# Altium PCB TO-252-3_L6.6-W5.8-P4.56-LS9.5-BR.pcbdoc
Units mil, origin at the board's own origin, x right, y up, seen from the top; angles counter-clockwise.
Board outline 938.23 x 780 mil, 2 copper layers (Top Layer, Bottom Layer), stack 0 mil thick; 1 components, 0 nets, 3 pads, 0 vias.
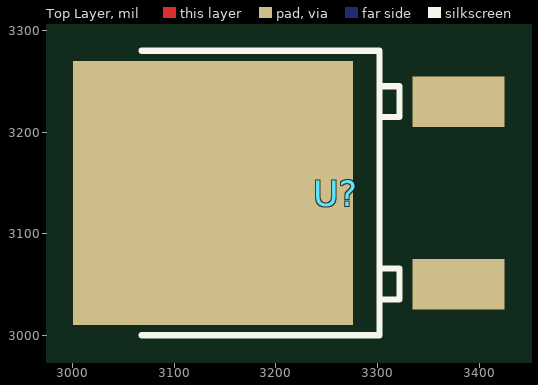
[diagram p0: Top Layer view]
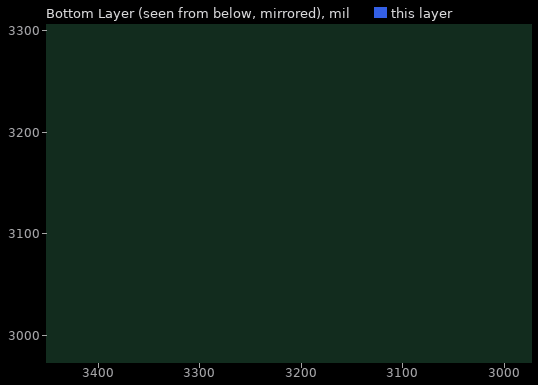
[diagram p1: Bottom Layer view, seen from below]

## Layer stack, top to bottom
Top Layer: signal copper (thickness not stored)
Bottom Layer: signal copper (thickness not stored)

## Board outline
3688.23,2750 2750,2750 2750,3530 3688.23,3530

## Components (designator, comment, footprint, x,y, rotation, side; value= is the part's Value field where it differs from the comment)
U? "" TO-252-3_L6.6-W5.8-P4.56-LS9.5-BR 3258.7,3140 r0 top

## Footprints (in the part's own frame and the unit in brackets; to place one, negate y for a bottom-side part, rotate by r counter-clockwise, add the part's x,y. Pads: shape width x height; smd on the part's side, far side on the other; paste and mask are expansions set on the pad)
TO-252-3_L6.6-W5.8-P4.56-LS9.5-BR [mm]
  rect 2.3x1.27 smd: 1(3.071,-2.28) 3(3.071,2.28)
  rect 7x6.6 smd: 2(-3.071,0)
  silkscreen extent -4.86,-3.56 1.59,3.56

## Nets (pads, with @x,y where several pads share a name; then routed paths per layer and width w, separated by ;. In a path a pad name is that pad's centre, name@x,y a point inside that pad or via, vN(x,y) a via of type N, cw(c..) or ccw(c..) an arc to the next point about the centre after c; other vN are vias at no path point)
pads on no net: U?.1 U?.2 U?.3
